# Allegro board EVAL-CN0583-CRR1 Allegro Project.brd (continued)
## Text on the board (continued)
Ref Des/Silkscreen Bottom: POWER SUPPLY | EXTERNAL | CR123A | + | _ | EVAL-CN0583-CRR1 | OFF | MICRO-SD | ENABLE | ON | C | A | USB POWER | EXT. SUPPLY | BATTERY | SELECT | VBATT
User.Comments: 5.    BOARDS TO BE SHIPPED SINGULATED AFTER ASSEMBLY PROCESS. | 6.    SMOOTHEN EDGES AND FREE FROM BURRS AFTER DEPANELIZATION PROCESS. | 7.    SHUNT M036050 TO BE INSTALLED TO THE FOLLOWING JUMPER  (SECONDARY SIDE). | 8.    ADD SOLDER BLOB AT PINS 2 & 3 OF JP3. | JP2: PIN 2 AND 3. | JP1: PIN 1 AND 2.
Ref Des/Assembly Top: GND | C | A
Ref Des/Silkscreen Top: C | EVAL-CN0583-CRR1 | A
DIMENSION: SEE DETAIL A | AT 7 PLACES | DETAIL A | BOARD CUT OUT | DIA MAX | " " | (REF)
PAGE_OUTLINE: B | C | D | ECR-113179 | ECR-115063 | ECR-117270 | 05APR23 | 09AUG23 | 29SEP23 | A. UY | CUSTOMER EVAL Z
User.15: PANEL TO BE SUBJECTED TO CUSTOMER'S APPROVAL. | PANELED SOLDER PASTE STENCIL SHOULD BE SENT TO THE CUSTOMER. | 15.    BOARDS TO BE SHIPPED IN ARRAY AND KEEP INTACT. | NOTE: ALL IMPEDANCE TOLERANCE +/-10% | LAYER | L1 | L4 | DP = DIFFERENTIAL PAIR | 90 OHMS DP | IMPEDANCE | REFERENCE | L2 | L3 | LINE WIDTH | 0.254MM | 0.184MM | SPACE | IMPEDANCE TABLE
User.17: L2 GND | 08-      -07
User.18: L3 PWR | 08-      -08
User.23: L2 GND | 08-      -075
User.24: L3 PWR | 08-      -085
User.45: FIGURE | SIZE | 0.254 | 0.711 | 0.889 | 1.143 | 1.27 | 1.448 | 1.981 | 2.032 | 3.175 | 5.08 | DRILL CHART: TOP to BOTTOM | FINISHED HOLES IN MILLIMETERS | PLATED | NON-PLATED | QTY | 452 | 10 | 41 | 11 | 2 | 4 | 1 | TOLERANCE/NOTES
